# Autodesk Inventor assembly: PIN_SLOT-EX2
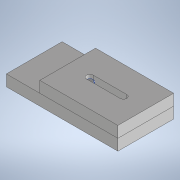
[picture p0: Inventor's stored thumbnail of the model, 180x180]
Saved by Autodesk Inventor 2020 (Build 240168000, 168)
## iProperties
Created: 2023-07
Part Number: PIN_SLOT-EX2
Document SubType Name: Assembly
Designer: chae-won
Author: chae-won
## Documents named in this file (4)
- C:\Users\chae-won\Desktop\설계도면\PIN_SLOT\PIN_SLOT-EX2.iam
- C:\Users\chae-won\Desktop\설계도면\PIN_SLOT\BASE.ipt
- C:\Users\chae-won\Desktop\설계도면\PIN_SLOT\PIN_8-12.ipt
- C:\Users\chae-won\Desktop\설계도면\PIN_SLOT\SLIDE.ipt
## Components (3 placed, 3 different names)
1. BASE:1 — 플러쉬:1, 플러쉬:2, 플러쉬:3
2. PIN_8-12:1 — 플러쉬:1
3. SLIDE:1 — 플러쉬:2, 플러쉬:3
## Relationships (3: Flush 3)
- 플러쉬:1 [Flush]: BASE:1 ↔ PIN_8-12:1
- 플러쉬:2 [Flush]: BASE:1 ↔ SLIDE:1
- 플러쉬:3 [Flush]: BASE:1 ↔ SLIDE:1
